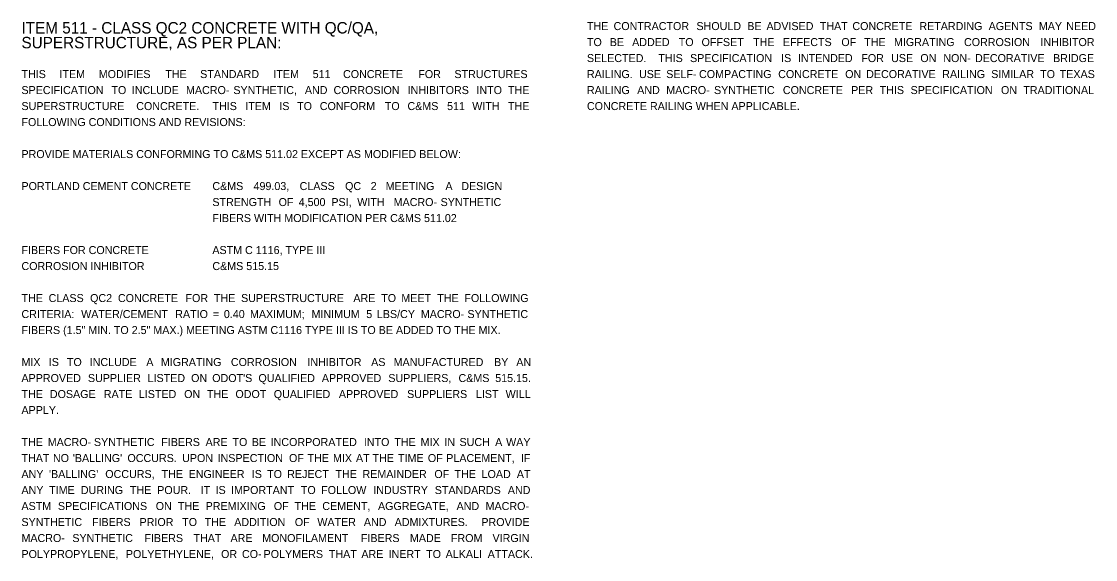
# Model space of a CAD drawing. Extents: x -19.8 to 34, y 0 to 22.
# Drawn here: x -19.82 to -1.03, y 11.73 to 21.15 of the extents above; entities that cross this region are included whole.
import ezdxf

# ---------------------------------------------------------------- set-up
doc = ezdxf.new("R2010")
doc.units = 0
for name, color, linetype in [('BR_P_Gen_Text', 7, 'Continuous'), ('SH_Text', 7, 'Continuous'), ('SN_P_Cantilever_Overhead', 7, 'Continuous')]:
    doc.layers.add(name, color=color, linetype=linetype)

msp = doc.modelspace()

# ---------------------------------------------------------------- texts
at = {"layer": 'BR_P_Gen_Text'}
for s, p in [('ITEM 511 - CLASS QC2 CONCRETE WITH QC/QA, ', (-19.82, 20.94)), ('SUPERSTRUCTURE, AS PER PLAN:', (-19.82, 20.681))]:
    msp.add_text(s, height=0.2, dxfattribs=at).set_placement(p)
at = {"layer": 'SH_Text'}
for s, p in [('THE ', (-9.927, 21)), ('CONTRACTOR ', (-9.461, 21)), ('SHOULD ', (-8.011, 21)), ('BE ', (-7.121, 21)), ('ADVISED ', (-6.786, 21)), ('THAT ', (-5.853, 21)), ('CONCRETE ', (-5.283, 21)), ('RETARDING ', (-4.111, 21)), ('AGENTS ', (-2.899, 21)), ('MAY ', (-2.021, 21)), ('NEED ', (-1.541, 21)), ('TO ', (-9.927, 20.72)), ('BE ', (-9.528, 20.72)), ('ADDED ', (-9.136, 20.72)), ('TO ', (-8.321, 20.72)), ('OFFSET ', (-7.922, 20.72)), ('THE ', (-7.02, 20.72)), ('EFFECTS ', (-6.498, 20.72)), ('OF ', (-5.476, 20.72)), ('THE ', (-5.077, 20.72)), ('MIGRATING ', (-4.555, 20.72)), ('CORROSION ', (-3.33, 20.72)), ('INHIBITOR ', (-1.993, 20.72)), ('SELECTED.  ', (-9.927, 20.44)), ('THIS ', (-8.677, 20.44)), ('SPECIFICATION ', (-8.123, 20.44)), ('IS ', (-6.529, 20.44)), ('INTENDED ', (-6.235, 20.44)), ('FOR ', (-5.127, 20.44)), ('USE ', (-4.605, 20.44)), ('ON ', (-4.094, 20.44)), ('NON-', (-3.692, 20.44)), ('DECORATIVE ', (-3.138, 20.44)), ('BRIDGE ', (-1.772, 20.44)), ('THIS ', (-19.82, 20.16)), ('ITEM ', (-19.155, 20.16)), ('MODIFIES ', (-18.468, 20.16)), ('THE ', (-17.304, 20.16)), ('STANDARD ', (-16.693, 20.16)), ('ITEM ', (-15.412, 20.16)), ('511 ', (-14.725, 20.16)), ('CONCRETE ', (-14.194, 20.16)), ('FOR ', (-12.877, 20.16)), ('STRUCTURES ', (-12.245, 20.16)), ('RAILING. ', (-9.927, 20.16)), ('USE ', (-9.016, 20.16)), ('SELF-', (-8.54, 20.16)), ('COMPACTING ', (-7.966, 20.16)), ('CONCRETE ', (-6.581, 20.16)), ('ON ', (-5.409, 20.16)), ('DECORATIVE ', (-5.042, 20.16)), ('RAILING ', (-3.711, 20.16)), ('SIMILAR ', (-2.854, 20.16)), ('TO ', (-1.998, 20.16)), ('TEXAS ', (-1.656, 20.16)), ('SPECIFICATION ', (-19.82, 19.88)), ('TO ', (-18.246, 19.88)), ('INCLUDE ', (-17.889, 19.88)), ('MACRO-', (-16.941, 19.88)), ('SYNTHETIC, ', (-16.113, 19.88)), ('AND ', (-14.862, 19.88)), ('CORROSION ', (-14.36, 19.88)), ('INHIBITORS ', (-13.064, 19.88)), ('INTO ', (-11.86, 19.88)), ('THE ', (-11.307, 19.88)), ('RAILING ', (-9.927, 19.88)), ('AND ', (-9.048, 19.88)), ('MACRO-', (-8.539, 19.88)), ('SYNTHETIC ', (-7.704, 19.88)), ('CONCRETE ', (-6.499, 19.88)), ('PER ', (-5.305, 19.88)), ('THIS ', (-4.806, 19.88)), ('SPECIFICATION ', (-4.265, 19.88)), ('ON ', (-2.683, 19.88)), ('TRADITIONAL ', (-2.293, 19.88)), ('SUPERSTRUCTURE ', (-19.82, 19.6)), ('CONCRETE.  ', (-17.812, 19.6)), ('THIS ', (-16.478, 19.6)), ('ITEM ', (-15.904, 19.6)), ('IS ', (-15.309, 19.6)), ('TO ', (-14.997, 19.6)), ('CONFORM ', (-14.601, 19.6)), ('TO ', (-13.463, 19.6)), ('C&MS ', (-13.067, 19.6)), ('511 ', (-12.374, 19.6)), ('WITH ', (-11.934, 19.6)), ('THE ', (-11.307, 19.6)), ('CONCRETE RAILING WHEN APPLICABLE.', (-9.927, 19.6)), ('FOLLOWING CONDITIONS AND REVISIONS:', (-19.82, 19.32)), ('PROVIDE MATERIALS CONFORMING TO C&MS 511.02 EXCEPT AS MODIFIED BELOW:', (-19.82, 18.76)), ('PORTLAND CEMENT CONCRETE', (-19.82, 18.2)), ('FIBERS FOR CONCRETE', (-19.82, 17.08)), ('CORROSION INHIBITOR', (-19.82, 16.8)), ('THE ', (-19.82, 16.24)), ('CLASS ', (-19.345, 16.24)), ('QC2 ', (-18.619, 16.24)), ('CONCRETE ', (-18.132, 16.24)), ('FOR ', (-16.95, 16.24)), ('THE ', (-16.453, 16.24)), ('SUPERSTRUCTURE ', (-15.978, 16.24)), ('ARE ', (-14.013, 16.24)), ('TO ', (-13.526, 16.24)), ('MEET ', (-13.174, 16.24)), ('THE ', (-12.546, 16.24)), ('FOLLOWING ', (-12.071, 16.24)), ('CRITERIA: ', (-19.82, 15.96)), ('WATER/CEMENT ', (-18.776, 15.96)), ('RATIO ', (-17.13, 15.96)), ('= ', (-16.47, 15.96)), ('0.40 ', (-16.279, 15.96)), ('MAXIMUM; ', (-15.822, 15.96)), ('MINIMUM ', (-14.745, 15.96)), ('5 ', (-13.788, 15.96)), ('LBS/CY ', (-13.602, 15.96)), ('MACRO-', (-12.833, 15.96)), ('SYNTHETIC ', (-12.017, 15.96)), ('FIBERS (1.5" MIN. TO 2.5" MAX.) MEETING ASTM C1116 TYPE III IS TO BE ADDED TO THE MIX.', (-19.82, 15.68)), ('MIX ', (-19.82, 15.12)), ('IS ', (-19.341, 15.12)), ('TO ', (-19.025, 15.12)), ('INCLUDE ', (-18.626, 15.12)), ('A ', (-17.636, 15.12)), ('MIGRATING ', (-17.381, 15.12)), ('CORROSION ', (-16.156, 15.12)), ('INHIBITOR ', (-14.818, 15.12)), ('AS ', (-13.702, 15.12)), ('MANUFACTURED ', (-13.309, 15.12)), ('BY ', (-11.552, 15.12)), ('AN ', (-11.163, 15.12)), ('APPROVED ', (-19.82, 14.84)), ('SUPPLIER ', (-18.657, 14.84)), ('LISTED ', (-17.613, 14.84)), ('ON ', (-16.852, 14.84)), ("ODOT'S ", (-16.483, 14.84)), ('QUALIFIED ', (-15.674, 14.84)), ('APPROVED ', (-14.565, 14.84)), ('SUPPLIERS, ', (-13.402, 14.84)), ('C&MS ', (-12.174, 14.84)), ('515.15.    ', (-11.532, 14.84)), ('THE ', (-19.82, 14.56)), ('DOSAGE ', (-19.323, 14.56)), ('RATE ', (-18.379, 14.56)), ('LISTED ', (-17.766, 14.56)), ('ON ', (-16.974, 14.56)), ('THE ', (-16.575, 14.56)), ('ODOT ', (-16.077, 14.56)), ('QUALIFIED ', (-15.406, 14.56)), ('APPROVED ', (-14.267, 14.56)), ('SUPPLIERS ', (-13.073, 14.56)), ('LIST ', (-11.869, 14.56)), ('WILL ', (-11.35, 14.56)), ('APPLY.  ', (-19.82, 14.28)), ('THE ', (-19.82, 13.72)), ('MACRO-', (-19.36, 13.72)), ('SYNTHETIC ', (-18.552, 13.72)), ('FIBERS ', (-17.374, 13.72)), ('ARE ', (-16.599, 13.72)), ('TO ', (-16.128, 13.72)), ('BE ', (-15.791, 13.72)), ('INCORPORATED ', (-15.461, 13.72)), ('INTO ', (-13.83, 13.72)), ('THE ', (-13.297, 13.72)), ('MIX ', (-12.837, 13.72)), ('IN ', (-12.421, 13.72)), ('SUCH ', (-12.156, 13.72)), ('A ', (-11.533, 13.72)), ('WAY ', (-11.341, 13.72)), ('THAT ', (-19.82, 13.44)), ('NO ', (-19.269, 13.44)), ("'BALLING' ", (-18.921, 13.44)), ('OCCURS. ', (-17.966, 13.44)), ('UPON ', (-17.009, 13.44)), ('INSPECTION ', (-16.389, 13.44)), ('OF ', (-15.139, 13.44)), ('THE ', (-14.816, 13.44)), ('MIX ', (-14.37, 13.44)), ('AT ', (-13.968, 13.44)), ('THE ', (-13.678, 13.44)), ('TIME ', (-13.232, 13.44)), ('OF ', (-12.71, 13.44)), ('PLACEMENT, ', (-12.388, 13.44)), ('IF ', (-11.083, 13.44)), ('ANY ', (-19.82, 13.16)), ("'BALLING' ", (-19.338, 13.16)), ('OCCURS, ', (-18.354, 13.16)), ('THE ', (-17.369, 13.16)), ('ENGINEER ', (-16.895, 13.16)), ('IS ', (-15.79, 13.16)), ('TO ', (-15.522, 13.16)), ('REJECT ', (-15.171, 13.16)), ('THE ', (-14.327, 13.16)), ('REMAINDER ', (-13.853, 13.16)), ('OF ', (-12.596, 13.16)), ('THE ', (-12.244, 13.16)), ('LOAD ', (-11.77, 13.16)), ('AT ', (-11.154, 13.16)), ('ANY ', (-19.82, 12.88)), ('TIME ', (-19.335, 12.88)), ('DURING ', (-18.781, 12.88)), ('THE ', (-17.923, 12.88)), ('POUR.  ', (-17.445, 12.88)), ('IT ', (-16.684, 12.88)), ('IS ', (-16.424, 12.88)), ('IMPORTANT ', (-16.153, 12.88)), ('TO ', (-14.932, 12.88)), ('FOLLOW ', (-14.577, 12.88)), ('INDUSTRY ', (-13.665, 12.88)), ('STANDARDS ', (-12.589, 12.88)), ('AND ', (-11.311, 12.88)), ('ASTM ', (-19.82, 12.6)), ('SPECIFICATIONS ', (-19.182, 12.6)), ('ON ', (-17.471, 12.6)), ('THE ', (-17.083, 12.6)), ('PREMIXING ', (-16.598, 12.6)), ('OF ', (-15.405, 12.6)), ('THE ', (-15.042, 12.6)), ('CEMENT, ', (-14.557, 12.6)), ('AGGREGATE, ', (-13.582, 12.6)), ('AND ', (-12.208, 12.6)), ('MACRO-', (-11.7, 12.6)), ('SYNTHETIC ', (-19.82, 12.32)), ('FIBERS ', (-18.586, 12.32)), ('PRIOR ', (-17.754, 12.32)), ('TO ', (-17.008, 12.32)), ('THE ', (-16.615, 12.32)), ('ADDITION ', (-16.098, 12.32)), ('OF ', (-15.038, 12.32)), ('WATER ', (-14.644, 12.32)), ('AND ', (-13.83, 12.32)), ('ADMIXTURES.  ', (-13.291, 12.32)), ('PROVIDE ', (-11.774, 12.32)), ('MACRO-', (-19.82, 12.04)), ('SYNTHETIC ', (-18.93, 12.04)), ('FIBERS ', (-17.669, 12.04)), ('THAT ', (-16.811, 12.04)), ('ARE ', (-16.163, 12.04)), ('MONOFILAMENT ', (-15.609, 12.04)), ('FIBERS ', (-13.882, 12.04)), ('MADE ', (-13.024, 12.04)), ('FROM ', (-12.307, 12.04)), ('VIRGIN ', (-11.579, 12.04)), ('POLYPROPYLENE, ', (-19.82, 11.76)), ('POLYETHYLENE, ', (-17.993, 11.76)), ('OR ', (-16.328, 11.76)), ('CO-', (-15.962, 11.76)), ('POLYMERS ', (-15.584, 11.76)), ('THAT ', (-14.442, 11.76)), ('ARE ', (-13.873, 11.76)), ('INERT ', (-13.397, 11.76)), ('TO ', (-12.74, 11.76)), ('ALKALI ', (-12.399, 11.76)), ('ATTACK.  ', (-11.663, 11.76))]:
    msp.add_text(s, height=0.14, dxfattribs=at).set_placement(p)
at = {"layer": 'SN_P_Cantilever_Overhead'}
for s, p in [('C&MS ', (-16.48, 18.2)), ('499.03, ', (-15.76, 18.2)), ('CLASS ', (-14.954, 18.2)), ('QC ', (-14.158, 18.2)), ('2 ', (-13.711, 18.2)), ('MEETING ', (-13.448, 18.2)), ('A ', (-12.403, 18.2)), ('DESIGN ', (-12.125, 18.2)), ('STRENGTH ', (-16.48, 17.92)), ('OF ', (-15.321, 17.92)), ('4,500 ', (-14.97, 17.92)), ('PSI, ', (-14.398, 17.92)), ('WITH  ', (-13.945, 17.92)), ('MACRO-', (-13.309, 17.92)), ('SYNTHETIC ', (-12.487, 17.92)), ('FIBERS WITH MODIFICATION PER C&MS 511.02', (-16.48, 17.64)), ('ASTM C 1116, TYPE III', (-16.48, 17.08)), ('C&MS 515.15', (-16.48, 16.8))]:
    msp.add_text(s, height=0.14, dxfattribs=at).set_placement(p)

doc.saveas('drawing.dxf')
